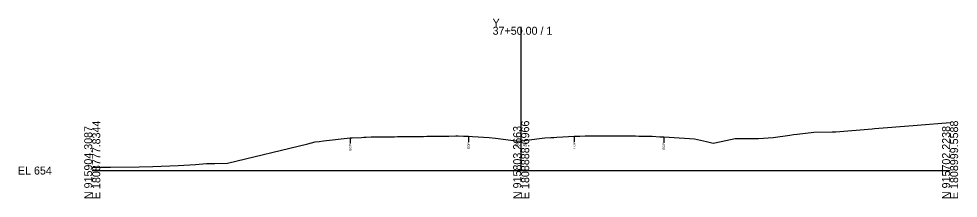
# Model space of a CAD drawing. Extents: x -26 to 3303, y -30 to 9580.
# Drawn here: x 1974.3 to 2302.8, y 7490.3 to 7553.1 of the extents above; entities that cross this region are included whole.
import ezdxf

# ---------------------------------------------------------------- set-up
doc = ezdxf.new("R2010")
doc.units = 0
for name, color, linetype in [('Exist Cross Section Cell', 7, 'Continuous'), ('Exist XS Center Line Elevation Label', 7, 'Continuous'), ('Exist XS Ground Line', 7, 'Continuous'), ('Old_Level_10', 7, 'Continuous')]:
    doc.layers.add(name, color=color, linetype=linetype)

msp = doc.modelspace()

# ---------------------------------------------------------------- linework, layer by layer
at = {"layer": 'Exist Cross Section Cell'}
for p, q in [((2150, 7500), (2150, 7550.34)), ((2000, 7500), (2150, 7500)), ((2150, 7500), (2300, 7500))]:
    msp.add_line(p, q, dxfattribs=at)
at = {"layer": 'Exist XS Ground Line'}
msp.add_lwpolyline([(2000, 7501.1), (2002.93, 7501.19), (2004.58, 7501.2), (2006.4, 7501.18), (2016.46, 7501.3), (2021.24, 7501.45), (2029.99, 7501.75), (2036.09, 7502.16), (2039.98, 7502.46), (2042.89, 7502.48), (2047.28, 7502.59), (2075.36, 7509.41), (2077.94, 7510.03), (2079.36, 7510.19), (2080.9, 7510.38), (2090.19, 7511.47), (2090.89, 7511.47), (2094.18, 7511.62), (2094.95, 7511.72), (2095.79, 7511.74), (2097.57, 7511.77), (2098.33, 7511.78), (2100.96, 7511.83), (2102.03, 7511.84), (2103.75, 7511.85), (2104.28, 7511.85), (2104.72, 7511.85), (2105.72, 7511.86), (2106.78, 7511.88), (2107.73, 7511.89), (2108.55, 7511.9), (2109.43, 7511.91), (2110.31, 7511.92), (2111.11, 7511.92), (2112.09, 7511.93), (2113.16, 7511.94), (2114.49, 7511.95), (2115.8, 7511.96), (2117.02, 7512), (2117.89, 7512.02), (2119.17, 7512.03), (2120.56, 7512.05), (2121.28, 7512.06), (2122.71, 7512.07), (2124.65, 7512.09), (2127.18, 7512.12), (2127.58, 7512.12), (2128.02, 7512.11), (2129.78, 7512.01), (2131.61, 7512), (2132.92, 7511.93), (2138.78, 7511.61), (2141.04, 7511.33), (2149.06, 7510.34), (2150, 7510.45), (2151.92, 7510.67), (2158.24, 7511.4), (2160.32, 7511.54), (2160.74, 7511.56), (2161.37, 7511.6), (2162.43, 7511.67), (2164.59, 7511.81), (2168.58, 7512.06), (2170.46, 7512.07), (2172.37, 7512.19), (2173.02, 7512.18), (2175.36, 7512.18), (2176.23, 7512.18), (2177.56, 7512.19), (2178.74, 7512.18), (2179.96, 7512.18), (2181.08, 7512.18), (2182.13, 7512.17), (2184.15, 7512.16), (2185.52, 7512.14), (2187.36, 7512.12), (2188.88, 7512.11), (2189.96, 7512.1), (2191.1, 7512.09), (2191.71, 7512.08), (2192.29, 7512.07), (2194.81, 7512.04), (2195.76, 7512.03), (2198.53, 7511.86), (2198.93, 7511.85), (2199.89, 7511.81), (2201.75, 7511.68), (2210.57, 7511.12), (2214.77, 7510.14), (2217.13, 7509.56), (2219.96, 7510.19), (2224.8, 7511.18), (2230.46, 7511.19), (2231.1, 7511.21), (2232.95, 7511.26), (2238.18, 7511.52), (2243.92, 7512.4), (2245.26, 7512.6), (2246.48, 7512.74), (2252.34, 7513.42), (2258.77, 7513.56), (2259.41, 7513.6), (2260.01, 7513.61), (2272.77, 7514.66), (2273.61, 7514.72), (2287.07, 7515.75), (2288.46, 7515.86), (2300, 7516.78)], dxfattribs=at)
at = {"layer": 'Old_Level_10'}
for p, q in [((2090.19, 7511.47), (2090.19, 7509.42)), ((2131.61, 7512), (2131.61, 7509.95)), ((2168.58, 7512.06), (2168.58, 7510.01)), ((2199.89, 7511.81), (2199.89, 7509.76))]:
    msp.add_line(p, q, dxfattribs=at)

# ---------------------------------------------------------------- texts
at = {"layer": 'Exist Cross Section Cell'}
for s, p in [('Y', (2140, 7550.34)), ('37+50.00 / 1', (2140, 7547.54)), ('EL 654', (1974, 7498.6))]:
    msp.add_text(s, height=2.8, dxfattribs=at).set_placement(p)
for s, p in [('E 1808777.8344', (2002.8, 7490)), ('E 1808888.6966', (2152.8, 7490)), ('E 1808999.5588', (2302.8, 7490)), ('N 915904.3087', (2000, 7490)), ('N 915803.2663', (2150, 7490)), ('N 915702.2238', (2300, 7490))]:
    msp.add_text(s, height=2.8, rotation=90, dxfattribs=at).set_placement(p)
at = {"layer": 'Exist XS Center Line Elevation Label'}
msp.add_text('664.45', height=1, dxfattribs=at).set_placement((2147.87, 7508.45))
at = {"layer": 'Old_Level_10'}
for p in [(2090.59, 7507.02), (2132.01, 7507.55), (2168.98, 7507.62), (2200.29, 7507.36)]:
    msp.add_text('EOP', height=0.787, rotation=90, dxfattribs=at).set_placement(p)

doc.saveas('drawing.dxf')
